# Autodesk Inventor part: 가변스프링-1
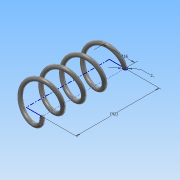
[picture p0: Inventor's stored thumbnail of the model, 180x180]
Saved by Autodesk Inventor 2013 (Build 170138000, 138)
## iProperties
Created: 2015-09
Part Number: 가변스프링-1
Material: 강철, 탄소
Document SubType Name: Modeling
Designer: Administrator
Density: 7.87 g/cm^3
Mass: 4.9226 g
Surface Area: 12.7485 cm^2
Volume: 0.62549 cm^3
Author: Administrator
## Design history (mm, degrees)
sketch "스케치1"
  geometry: L1 (0, 0)-(8, 0); L2 (8, 0)-(8, 42); L3 (8, 42)-(0, 42); L4 (0, 42)-(0, 0); C1 r 1 at (8, 42)
  constraints: 8 end point, 2 parallel, 1 centre point, 1 coincident, 1 horizontal, 1 perpendicular
  dimensions: "d0" = 16 diameter of L2 L4; "d2" = 42 distance between parallel lines of L1 L3 (derived); "d3" = 2 diameter of C1
feature "코일1" pitch "d4" = 10; turns "d6" = 4; dims "d5" = 42 (= d2), "d7" = 0, angle "d8" = 90 deg, angle "d9" = 90 deg, "d10" = 0, "d11" = 0
feature "분할1"
node "작업 평면1"
feature "분할2"
node "솔리드1"
other parameters: "d12" = 90 deg
